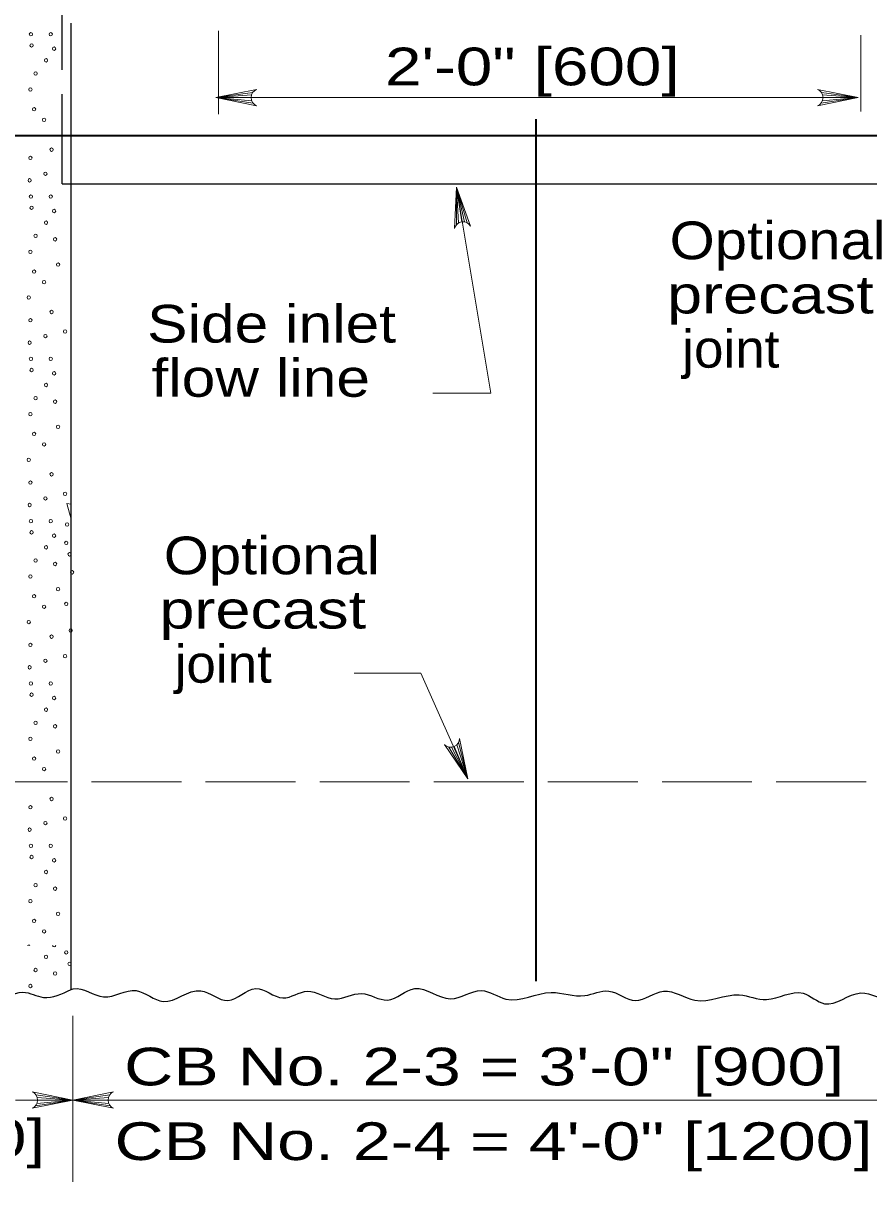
# Model space of a CAD drawing. Extents: x 1083.1 to 1117.1, y 697.4 to 719.4.
# Drawn here: x 1094.585 to 1098.084, y 710.545 to 715.339 of the extents above; entities that cross this region are included whole.
import ezdxf
from ezdxf.enums import TextEntityAlignment as Align

# ---------------------------------------------------------------- set-up
doc = ezdxf.new("R2010")
doc.units = 0
doc.header["$LTSCALE"] = 0.062
doc.linetypes.add('LONG_DASHED', pattern=[7.5, 6, -1.5])
doc.layers.add('1', color=7, linetype='Continuous', lineweight=13)

msp = doc.modelspace()

# ---------------------------------------------------------------- linework, layer by layer
at = {"layer": '1', "linetype": 'LONG_DASHED', "lineweight": 25}
for q in [(1094.74617, 715.37608), (1094.78358, 714.6735)]:
    msp.add_line((1094.74617, 714.6735), q, dxfattribs=at)
at = {"layer": '1', "lineweight": 25}
for p, q in [((1094.78358, 711.34008), (1094.78358, 715.33867)), ((1094.78358, 714.6735), (1098.65942, 714.6735))]:
    msp.add_line(p, q, dxfattribs=at)
at = {"layer": '1'}
for p, q in [((1095.39367, 714.962), (1095.39367, 715.30658)), ((1098.05058, 715.28875), (1098.05058, 714.9735)), ((1095.53525, 715.05217), (1095.38292, 715.03092)), ((1095.53008, 715.04167), (1095.38292, 715.03092)), ((1097.88758, 715.05217), (1098.03983, 715.03092)), ((1097.89275, 715.04167), (1098.03983, 715.03092)), ((1095.38292, 715.03092), (1096.9545, 715.03092)), ((1095.5285, 715.03092), (1095.38292, 715.03092)), ((1095.53117, 715.01717), (1095.38292, 715.03092)), ((1095.537, 715.00733), (1095.38292, 715.03092)), ((1096.9545, 715.03092), (1098.03983, 715.03092)), ((1097.88575, 715.00733), (1098.03983, 715.03092)), ((1097.89158, 715.01717), (1098.03983, 715.03092)), ((1097.89425, 715.03092), (1098.03983, 715.03092)), ((1096.378, 714.50475), (1096.37867, 714.66067)), ((1096.4, 714.51667), (1096.37867, 714.66067)), ((1096.38683, 714.512), (1096.37867, 714.66067)), ((1096.41092, 714.51667), (1096.37867, 714.66067)), ((1096.42208, 714.51308), (1096.37867, 714.66067)), ((1096.37867, 714.66067), (1096.52008, 713.8075)), ((1096.52008, 713.8075), (1096.28025, 713.8075)), ((1094.76633, 713.35175), (1094.7835, 713.28667)), ((1094.7835, 713.34833), (1094.76633, 713.35175)), ((1096.37992, 712.35333), (1096.42475, 712.21133)), ((1096.38675, 712.3625), (1096.42475, 712.21133)), ((1096.34608, 712.3435), (1096.42475, 712.21133)), ((1096.35783, 712.34283), (1096.42475, 712.21133)), ((1096.36833, 712.34558), (1096.42475, 712.21133)), ((1094.79117, 711.23125), (1094.79117, 710.54458)), ((1094.811, 710.88275), (1094.55308, 710.88275)), ((1094.6365, 710.85917), (1094.79058, 710.88275)), ((1094.63825, 710.90408), (1094.79058, 710.88275)), ((1094.64233, 710.86908), (1094.79058, 710.88275)), ((1094.64342, 710.8935), (1094.79058, 710.88275)), ((1094.645, 710.88275), (1094.79058, 710.88275)), ((1094.94333, 710.90408), (1094.791, 710.88275)), ((1094.93817, 710.8935), (1094.791, 710.88275)), ((1094.93658, 710.88275), (1094.791, 710.88275)), ((1094.93925, 710.86908), (1094.791, 710.88275)), ((1094.94508, 710.85917), (1094.791, 710.88275)), ((1098.3885, 710.88275), (1094.811, 710.88275))]:
    msp.add_line(p, q, dxfattribs=at)
at = {"layer": '1', "lineweight": 35}
msp.add_line((1093.45367, 714.874), (1100.04975, 714.874), dxfattribs=at)
at = {"layer": '1', "linetype": 'LONG_DASHED'}
msp.add_line((1094.39633, 712.19967), (1099.02808, 712.19967), dxfattribs=at)
at = {"layer": '1'}
for points in [[(1095.55117, 714.99725), (1095.38292, 715.03092), (1095.55117, 715.0645)], [(1097.87167, 714.99725), (1098.03983, 715.03092), (1097.87167, 715.0645)], [(1096.37008, 714.48933), (1096.37867, 714.66067), (1096.43658, 714.49917)], [(1096.42475, 712.21133), (1096.22992, 712.64925), (1095.95458, 712.64925)], [(1096.39058, 712.3795), (1096.42475, 712.21133), (1096.32858, 712.35342)], [(1094.62233, 710.84908), (1094.79058, 710.88275), (1094.62233, 710.91642)], [(1094.95925, 710.84908), (1094.791, 710.88275), (1094.95925, 710.91642)]]:
    msp.add_lwpolyline(points, dxfattribs=at)
at = {"layer": '1', "lineweight": 35}
msp.add_lwpolyline([(1096.70583, 714.94167), (1096.70583, 711.52217), (1096.70583, 711.37508)], dxfattribs=at)
at = {"layer": '1'}
for centre, start, end in [((1095.56474, 715.03092), 112.08782, 247.91395), ((1097.85805, 715.03092), 292.08605, 67.91218), ((1096.40537, 714.4808), 30.52667, 166.3528), ((1096.3543, 712.37895), 224.86313, 0.68926), ((1094.60874, 710.88279), 292.08605, 67.91218), ((1094.97279, 710.88279), 112.08782, 247.91395)]:
    msp.add_arc(centre, 0.03631, start, end, dxfattribs=at)
for centre in [(1094.61741, 715.29286), (1094.69968, 715.29286), (1094.61995, 715.24663), (1094.71337, 715.23303), (1094.6799, 715.18495), (1094.63682, 715.13027), (1094.61541, 715.06406), (1094.63084, 714.98245), (1094.67197, 714.9389), (1094.70306, 714.81532), (1094.61541, 714.78107), (1094.67731, 714.71553), (1094.61229, 714.68832), (1094.61741, 714.62121), (1094.69968, 714.62121), (1094.61995, 714.57498), (1094.71337, 714.56138), (1094.6799, 714.5133), (1094.63682, 714.45862), (1094.7176, 714.4444), (1094.61541, 714.39241), (1094.63084, 714.3108), (1094.73018, 714.33985), (1094.67197, 714.26726), (1094.60853, 714.20378), (1094.70306, 714.14367), (1094.61541, 714.10942), (1094.67731, 714.04388), (1094.75873, 714.06291), (1094.61229, 714.01667), (1094.61741, 713.94957), (1094.69968, 713.94957), (1094.61995, 713.90333), (1094.71337, 713.88973), (1094.6799, 713.84165), (1094.63682, 713.78697), (1094.7176, 713.77275), (1094.61541, 713.72076), (1094.63084, 713.63915), (1094.73018, 713.6682), (1094.67197, 713.59561), (1094.60853, 713.53214), (1094.70306, 713.47202), (1094.61541, 713.43777), (1094.67731, 713.37223), (1094.75873, 713.39126), (1094.61229, 713.34503), (1094.61741, 713.27792), (1094.69968, 713.27792), (1094.76729, 713.26432), (1094.61995, 713.23168), (1094.71337, 713.21808), (1094.6799, 713.17), (1094.76386, 713.18814), (1094.63682, 713.11532), (1094.7776, 713.14101), (1094.7176, 713.1011), (1094.7878, 713.06663), (1094.61541, 713.04911), (1094.63084, 712.9675), (1094.73018, 712.99655), (1094.67197, 712.92396), (1094.76359, 712.93577), (1094.60853, 712.86049), (1094.78188, 712.82573), (1094.70306, 712.80037), (1094.61541, 712.76612), (1094.67731, 712.70058), (1094.75873, 712.71961), (1094.61229, 712.67338), (1094.61741, 712.60627), (1094.69968, 712.60627), (1094.61995, 712.56004), (1094.71337, 712.54643), (1094.6799, 712.49836), (1094.63682, 712.44367), (1094.7176, 712.42946), (1094.61541, 712.37746), (1094.63084, 712.29585), (1094.73018, 712.3249), (1094.67197, 712.25231), (1094.70306, 712.12872), (1094.61541, 712.09447), (1094.67731, 712.02893), (1094.75873, 712.04796), (1094.61229, 712.00173), (1094.61741, 711.93462), (1094.69968, 711.93462), (1094.61995, 711.88839), (1094.71337, 711.87479), (1094.6799, 711.82671), (1094.63682, 711.77202), (1094.7176, 711.75781), (1094.61541, 711.70581), (1094.63084, 711.6242), (1094.73018, 711.65325), (1094.67197, 711.58066), (1094.76386, 711.49372), (1094.6799, 711.47558), (1094.7776, 711.44659), (1094.63682, 711.4209), (1094.7176, 711.40668), (1094.61541, 711.35469)]:
    msp.add_ellipse(centre, major_axis=(0, 0.00718), ratio=0.944544, dxfattribs=at)
for centre, start_param, end_param in [((1094.60853, 711.51719), 5.4808807, 7.0854899), ((1094.71337, 711.52366), 1.7785356, 4.5046496)]:
    msp.add_ellipse(centre, major_axis=(0, 0.00718), ratio=0.944544, start_param=start_param, end_param=end_param, dxfattribs=at)
at = {"layer": '1', "lineweight": 25}
for points in [[(1093.91333, 711.41925), (1093.964, 711.30275), (1094.03767, 711.33133), (1094.10658, 711.3025), (1094.18117, 711.332), (1094.265, 711.2885), (1094.37967, 711.328), (1094.45975, 711.303), (1094.58467, 711.329), (1094.6695, 711.30792), (1094.7835, 711.34008)], [(1094.7835, 711.34008), (1094.7925, 711.34258), (1094.91825, 711.31), (1095.0525, 711.33592), (1095.16525, 711.29067), (1095.31992, 711.33525), (1095.43267, 711.29475), (1095.54733, 711.344), (1095.66008, 711.30558), (1095.76175, 711.33333), (1095.87442, 711.30167), (1095.98533, 711.32358), (1096.0925, 711.29675), (1096.20533, 711.34408), (1096.35342, 711.30192), (1096.48108, 711.33567), (1096.58267, 711.301), (1096.77, 711.32808), (1096.90883, 711.31517), (1097.00767, 711.33408), (1097.1185, 711.29467), (1097.235, 711.33317), (1097.3645, 711.29575), (1097.54817, 711.318), (1097.66092, 711.299), (1097.81183, 711.325), (1097.90033, 711.28158), (1098.05042, 711.32617), (1098.17992, 711.28283), (1098.39475, 711.30733)]]:
    msp.add_spline(points, degree=3, dxfattribs=at)

# ---------------------------------------------------------------- texts
at = {"layer": '1'}
for s, width, p in [('2\'-0" [600]', 1.3, (1096.0825, 715.08142)), ('CB No. 2-3 = 3\'-0" [900]', 1.35, (1095.003, 710.9435)), ('CB No. 2-4 = 4\'-0" [1200]', 1.35, (1094.96342, 710.63475))]:
    msp.add_text(s, height=0.156, dxfattribs=dict(at, width=width)).set_placement(p)
for s, width, p in [('Optional', 1.15, (1097.70658, 714.36192)), ('precast', 1.25, (1097.67671, 714.13758)), ('Side inlet', 1.2, (1095.61312, 714.01708)), ('joint', 1.05, (1097.51308, 713.91333)), ('flow line', 1.2, (1095.56808, 713.79275)), ('Optional', 1.15, (1095.61392, 713.05825)), ('precast', 1.25, (1095.57654, 712.834)), ('joint', 1.05, (1095.413, 712.60967)), ('[200]', 1.35, (1094.364, 710.64767))]:
    msp.add_text(s, height=0.156, dxfattribs=dict(at, width=width)).set_placement(p, align=Align.CENTER)

doc.saveas('drawing.dxf')
